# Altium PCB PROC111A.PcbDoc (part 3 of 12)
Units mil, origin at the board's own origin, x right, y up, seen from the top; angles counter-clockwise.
Board outline 7700 x 2300 mil, 6 copper layers (Top Layer, GND 1, SIG 1, SIG 2, GND 2, Bottom Layer), stack 61.062 mil thick; 841 components, 632 nets, 2914 pads, 1627 vias.
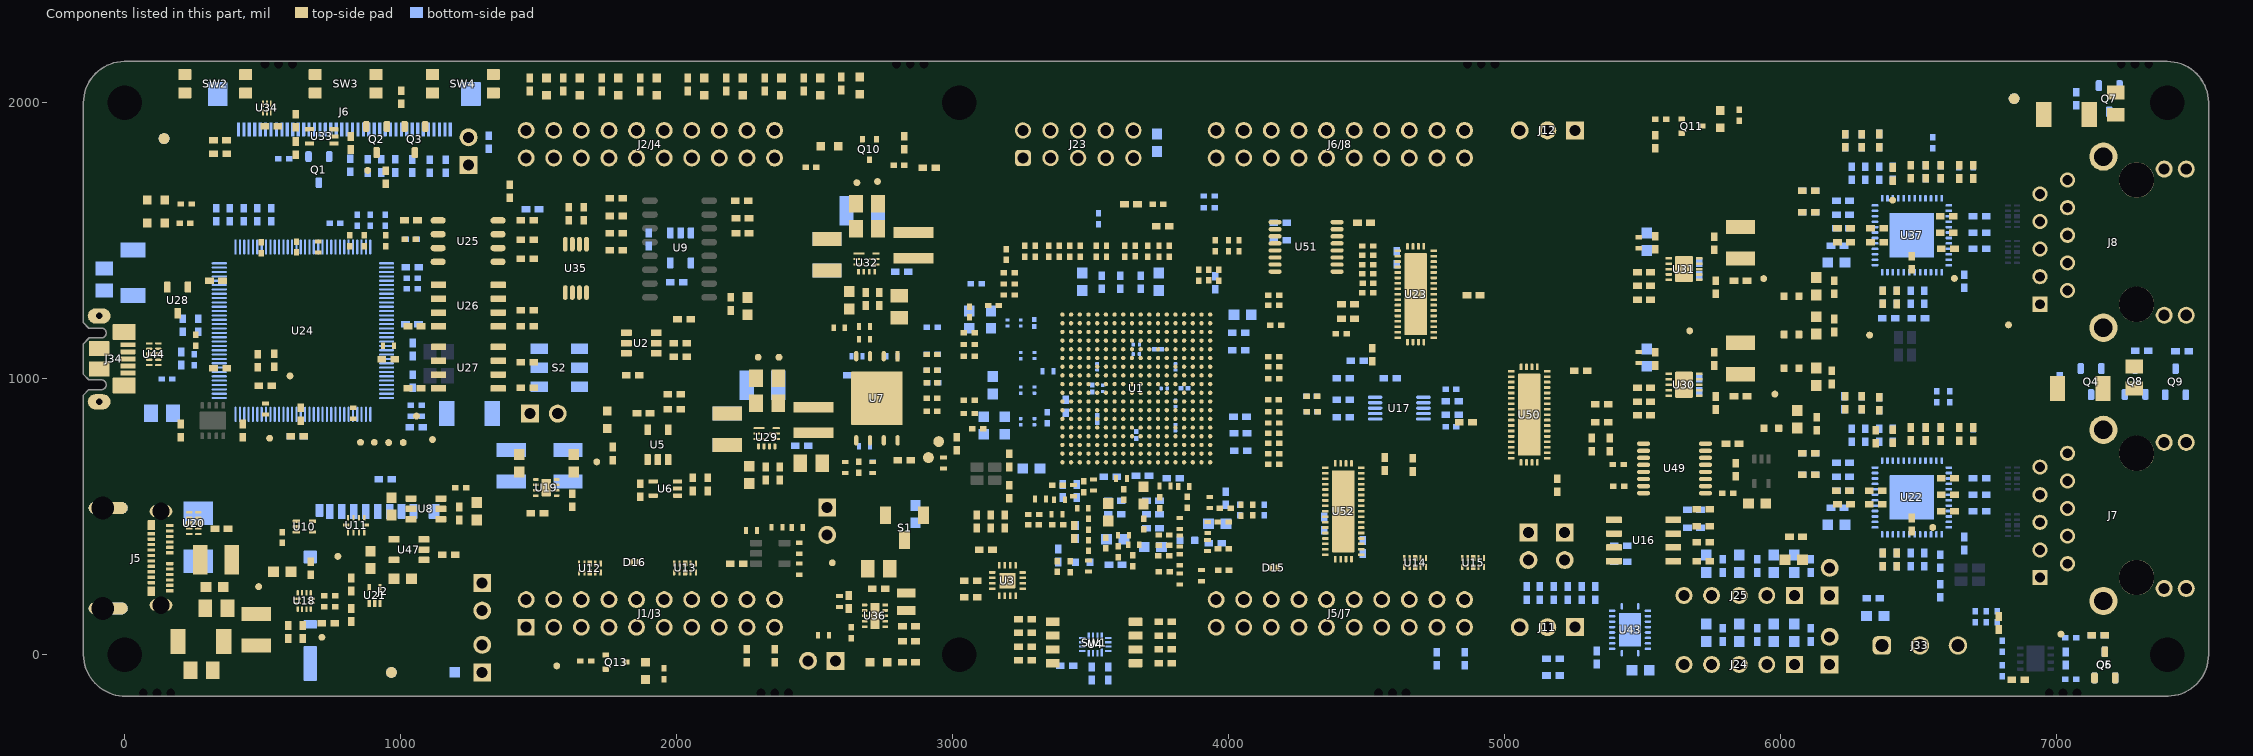
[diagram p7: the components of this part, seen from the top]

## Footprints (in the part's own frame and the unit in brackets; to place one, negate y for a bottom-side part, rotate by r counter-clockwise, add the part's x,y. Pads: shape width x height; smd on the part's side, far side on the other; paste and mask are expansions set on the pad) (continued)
PDT0128A [mm] "Thin QFP, 128-Leads, Body 14x14mm, Pitch 0.4mm"
  oval 1.4x0.2 smd: 1(-7.7,6.2) 2(-7.7,5.8) 3(-7.7,5.4) 4(-7.7,5) 5(-7.7,4.6) 6(-7.7,4.2) 7(-7.7,3.8) 8(-7.7,3.4) 9(-7.7,3) 10(-7.7,2.6) 11(-7.7,2.2) 12(-7.7,1.8) 13(-7.7,1.4) 14(-7.7,1) 15(-7.7,0.6) 16(-7.7,0.2) 17(-7.7,-0.2) 18(-7.7,-0.6) 19(-7.7,-1) 20(-7.7,-1.4) 21(-7.7,-1.8) 22(-7.7,-2.2) 23(-7.7,-2.6) 24(-7.7,-3) 25(-7.7,-3.4) 26(-7.7,-3.8) 27(-7.7,-4.2) 28(-7.7,-4.6) 29(-7.7,-5) 30(-7.7,-5.4) 31(-7.7,-5.8) 32(-7.7,-6.2) 65(7.7,-6.2) 66(7.7,-5.8) 67(7.7,-5.4) 68(7.7,-5) 69(7.7,-4.6) 70(7.7,-4.2) 71(7.7,-3.8) 72(7.7,-3.4) 73(7.7,-3) 74(7.7,-2.6) 75(7.7,-2.2) 76(7.7,-1.8) 77(7.7,-1.4) 78(7.7,-1) 79(7.7,-0.6) 80(7.7,-0.2) 81(7.7,0.2) 82(7.7,0.6) 83(7.7,1) 84(7.7,1.4) 85(7.7,1.8) 86(7.7,2.2) 87(7.7,2.6) 88(7.7,3) 89(7.7,3.4) 90(7.7,3.8) 91(7.7,4.2) 92(7.7,4.6) 93(7.7,5) 94(7.7,5.4) 95(7.7,5.8) 96(7.7,6.2)
  oval 0.2x1.4 smd: 33(-6.2,-7.7) 34(-5.8,-7.7) 35(-5.4,-7.7) 36(-5,-7.7) 37(-4.6,-7.7) 38(-4.2,-7.7) 39(-3.8,-7.7) 40(-3.4,-7.7) 41(-3,-7.7) 42(-2.6,-7.7) 43(-2.2,-7.7) 44(-1.8,-7.7) 45(-1.4,-7.7) 46(-1,-7.7) 47(-0.6,-7.7) 48(-0.2,-7.7) 49(0.2,-7.7) 50(0.6,-7.7) 51(1,-7.7) 52(1.4,-7.7) 53(1.8,-7.7) 54(2.2,-7.7) 55(2.6,-7.7) 56(3,-7.7) 57(3.4,-7.7) 58(3.8,-7.7) 59(4.2,-7.7) 60(4.6,-7.7) 61(5,-7.7) 62(5.4,-7.7) 63(5.8,-7.7) 64(6.2,-7.7) 97(6.2,7.7) 98(5.8,7.7) 99(5.4,7.7) 100(5,7.7) 101(4.6,7.7) 102(4.2,7.7) 103(3.8,7.7) 104(3.4,7.7) 105(3,7.7) 106(2.6,7.7) 107(2.2,7.7) 108(1.8,7.7) 109(1.4,7.7) 110(1,7.7) 111(0.6,7.7) 112(0.2,7.7) 113(-0.2,7.7) 114(-0.6,7.7) 115(-1,7.7) 116(-1.4,7.7) 117(-1.8,7.7) 118(-2.2,7.7) 119(-2.6,7.7) 120(-3,7.7) 121(-3.4,7.7) 122(-3.8,7.7) 123(-4.2,7.7) 124(-4.6,7.7) 125(-5,7.7) 126(-5.4,7.7) 127(-5.8,7.7) 128(-6.2,7.7)
  silkscreen extent -7.7,-6.3 6.3,6.99, body extent -8,-8 8,8, height 1.07
PW0016A_L [mm] "TSOP, 16-Leads, Body 5x4.4mm, Pitch 0.65mm, IPC High Density"
  oval 1.2x0.4 smd: 1(-2.85,2.275) 2(-2.85,1.625) 3(-2.85,0.975) 4(-2.85,0.325) 5(-2.85,-0.325) 6(-2.85,-0.975) 7(-2.85,-1.625) 8(-2.85,-2.275) 9(2.85,-2.275) 10(2.85,-1.625) 11(2.85,-0.975) 12(2.85,-0.325) 13(2.85,0.325) 14(2.85,0.975) 15(2.85,1.625) 16(2.85,2.275)
  silkscreen extent -2,-2.55 1.85,2.55, body extent -3.21,-2.5 3.21,2.5, height 1
RGT0016A [mm] "QFN, 16-Leads, Body 3x3mm, Pitch 0.5mm, Thermal Pad 1.45x1.45mm, TI Recommended"
  rrect42% 0.6x0.24 smd: 1(-1.4,0.75) 2(-1.4,0.25) 3(-1.4,-0.25) 4(-1.4,-0.75) 9(1.4,-0.75) 10(1.4,-0.25) 11(1.4,0.25) 12(1.4,0.75)
  rrect42% 0.24x0.6 smd: 5(-0.75,-1.4) 6(-0.25,-1.4) 7(0.25,-1.4) 8(0.75,-1.4) 13(0.75,1.4) 14(0.25,1.4) 15(-0.25,1.4) 16(-0.75,1.4)
  rrect7% 1.34x1.34 on Top Paste: 17(0,0)
  rrect7% 1.45x1.45 smd paste-0.725: 17(0,0)
  silkscreen extent -1.72,-1.73 1.72,1.73, body extent -1.5,-1.5 1.5,1.5, height 1
RGY0020A [mm] "QFN, 20-Leads, Body 4.5x3.5mm, Pitch 0.5mm, Thermal Pad 3.05x2.05mm, TI Recommended"
  oval 0.24x0.6 smd: 1(-0.75,2.15) 10(-0.75,-2.15) 11(0.75,-2.15) 20(0.75,2.15)
  oval 0.6x0.24 smd: 2(-1.65,1.75) 3(-1.65,1.25) 4(-1.65,0.75) 5(-1.65,0.25) 6(-1.65,-0.25) 7(-1.65,-0.75) 8(-1.65,-1.25) 9(-1.65,-1.75) 12(1.65,-1.75) 13(1.65,-1.25) 14(1.65,-0.75) 15(1.65,-0.25) 16(1.65,0.25) 17(1.65,0.75) 18(1.65,1.25) 19(1.65,1.75)
  rect 2.05x3.05 smd paste-1.025: 21(0,0)
  silkscreen extent -1.97,-2.47 1.97,2.48, body extent -1.75,-2.25 1.75,2.25, height 1
RGZ0048B-MFG [mm]
  rrect42% 0.6x0.24 smd paste+0 mask+0: 1(-3.4,2.75) 2(-3.4,2.25) 3(-3.4,1.75) 4(-3.4,1.25) 5(-3.4,0.75) 6(-3.4,0.25) 7(-3.4,-0.25) 8(-3.4,-0.75) 9(-3.4,-1.25) 10(-3.4,-1.75) 11(-3.4,-2.25) 12(-3.4,-2.75) 25(3.4,-2.75) 26(3.4,-2.25) 27(3.4,-1.75) 28(3.4,-1.25) 29(3.4,-0.75) 30(3.4,-0.25) 31(3.4,0.25) 32(3.4,0.75) 33(3.4,1.25) 34(3.4,1.75) 35(3.4,2.25) 36(3.4,2.75)
  rrect42% 0.24x0.6 smd paste+0 mask+0: 13(-2.75,-3.4) 14(-2.25,-3.4) 15(-1.75,-3.4) 16(-1.25,-3.4) 17(-0.75,-3.4) 18(-0.25,-3.4) 19(0.25,-3.4) 20(0.75,-3.4) 21(1.25,-3.4) 22(1.75,-3.4) 23(2.25,-3.4) 24(2.75,-3.4) 37(2.75,3.4) 38(2.25,3.4) 39(1.75,3.4) 40(1.25,3.4) 41(0.75,3.4) 42(0.25,3.4) 43(-0.25,3.4) 44(-0.75,3.4) 45(-1.25,3.4) 46(-1.75,3.4) 47(-2.25,3.4) 48(-2.75,3.4)
  rrect2% 4.1x4.1 smd paste-1000 mask+0: 49(0,0)
  silkscreen extent -4.38,-3.57 3.57,3.57, body extent -3.5,-3.5 3.5,3.5, height 1.02
RPU0010A-MFG [mm]
  rrect50% 0.65x0.2 smd paste+0 mask+0: 1(-0.875,0.25) 3(-0.875,-0.75) 5(0.875,-0.25)
  rrect50% 1x0.2 smd paste+0 mask+0: 2(-0.7,-0.25) 4(0.7,-0.75) 6(0.7,0.25)
  rrect40% 0.25x0.55 smd paste+0 mask+0: 7(0.75,0.925) 8(0.25,0.925) 9(-0.25,0.925) 10(-0.75,0.925)
  silkscreen extent -1.97,-1.5 1,1.6, body extent -1.3,-1.15 1.3,1.3, height 0.25
RSE0010A [mm] "QFN, 10-Leads, Body 1.5x2mm, Pitch 0.5mm, TI Recommended"
  rect 0.55x0.2 smd: 1(-0.675,0.75) 2(-0.675,0.25) 3(-0.675,-0.25) 4(-0.675,-0.75) 6(0.675,-0.75) 7(0.675,-0.25) 8(0.675,0.25) 9(0.675,0.75)
  rect 0.3x0.6 smd: 5(0,-0.9) 10(0,0.9)
  silkscreen extent -1.07,-1.17 0.77,1.18, body extent -0.77,-1.02 0.78,1.03, height 0.61
RSV0016A [mm] "QFN, 16-Leads, Body 1.8x2.6mm, Pitch 0.4mm, TI Recommended"
  rect 0.7x0.2 smd: 1(-0.75,0.6)
  rect 0.6x0.2 smd: 2(-0.8,0.2) 3(-0.8,-0.2) 4(-0.8,-0.6) 9(0.8,-0.6) 10(0.8,-0.2) 11(0.8,0.2) 12(0.8,0.6)
  rect 0.2x0.6 smd: 5(-0.6,-1.2) 6(-0.2,-1.2) 7(0.2,-1.2) 8(0.6,-1.2) 13(0.6,1.2) 14(0.2,1.2) 15(-0.2,1.2) 16(-0.6,1.2)
  silkscreen extent -1.08,-1.33 1.08,1.45, body extent -0.92,-1.32 0.92,1.33, height 0.56
RUA0042A-MFG [mm]
  rrect40% 0.6x0.25 smd paste+0 mask+0: 1(-1.65,4) 2(-1.65,3.5) 3(-1.65,3) 4(-1.65,2.5) 5(-1.65,2) 6(-1.65,1.5) 7(-1.65,1) 8(-1.65,0.5) 9(-1.65,0) 10(-1.65,-0.5) 11(-1.65,-1) 12(-1.65,-1.5) 13(-1.65,-2) 14(-1.65,-2.5) 15(-1.65,-3) 16(-1.65,-3.5) 17(-1.65,-4) 22(1.65,-4) 23(1.65,-3.5) 24(1.65,-3) 25(1.65,-2.5) 26(1.65,-2) 27(1.65,-1.5) 28(1.65,-1) 29(1.65,-0.5) 30(1.65,0) 31(1.65,0.5) 32(1.65,1) 33(1.65,1.5) 34(1.65,2) 35(1.65,2.5) 36(1.65,3) 37(1.65,3.5) 38(1.65,4)
  rrect40% 0.25x0.6 smd paste+0 mask+0: 18(-0.75,-4.4) 19(-0.25,-4.4) 20(0.25,-4.4) 21(0.75,-4.4) 39(0.75,4.4) 40(0.25,4.4) 41(-0.25,4.4) 42(-0.75,4.4)
  rrect5% 2.05x7.55 smd paste-1000 mask+0: 43(0,0)
  silkscreen extent -2.65,-4.55 1.8,4.55, body extent -2.05,-4.8 2.05,4.8, height 0.25
RWB0012A [mm] "QFN, 12-Leads, Body 1.6x1.6mm, Pitch 0.4mm"
  rrect57% 0.7x0.2 smd paste-0.1: 1(-0.65,0.2) 2(-0.65,-0.2) 7(0.65,-0.2) 8(0.65,0.2)
  rrect57% 0.2x0.5 smd: 3(-0.6,-0.75) 4(-0.2,-0.75) 5(0.2,-0.75) 6(0.6,-0.75) 9(0.6,0.75) 10(0.2,0.75) 11(-0.2,0.75) 12(-0.6,0.75)
  silkscreen extent -0.92,-0.91 0.92,0.91, body extent -0.8,-0.8 0.8,0.8, height 0.4
SMB-Bi [mil] "Molded Diode, 2-Leads, Body 5.4x3.6mm, IPC Medium Density, based on OnSemi component dimensions"
  rect 85x107.99 smd: 1(-87.01,0) 2(87.01,0)
  silkscreen extent -125,-79 125,79, body extent -104,-73 104,73, height 89
SOIC-8 [mm] "duplicate of SO-8.  SOIC, 8-Leads, Body 5.0x4.0mm (max), Pitch 1.27mm, IPC Medium Density"
  rrect17% 1.45x0.6 smd: 1(-2.725,1.905) 2(-2.725,0.635) 3(-2.725,-0.635) 4(-2.725,-1.905) 5(2.725,-1.905) 6(2.725,-0.635) 7(2.725,0.635) 8(2.725,1.905)
  silkscreen extent -3.5,-2.5 0.9,2.5, body extent -3,-2.45 3,2.45, height 1.63
SOT-23 [mm] "SOT23, 3-Leads, Body 2.9x1.3mm, Pitch 0.95mm, Lead Span 2.5mm, IPC Medium Density"
  rrect50% 1x0.6 smd: 1(-1.2,0.95) 2(-1.2,-0.95) 3(1.2,0)
  silkscreen extent -1.63,-1.5 0.7,1.5, body extent -1.16,-1.45 1.21,1.45, height 1
SOT-323 [mm] "Diodes Inc recommended land pattern.  2016-02-24"
  rrect21% 0.6x0.47 smd: 1(-0.95,0.65) 2(-0.95,-0.65) 3(0.95,0)
  silkscreen extent -1.14,-1.22 0.77,1.22, body extent -1.13,-1.13 1.12,1.12, height 1.13
Sullins_PBC02SAAN [mm] "Sullins 100mil, 1x2, 230 mil above insulator"
  rect 1.65x1.65 hole 1.016: 1(0,1.27)
  round 1.65 hole 1.016: 2(0,-1.27)
  silkscreen extent -1.37,-2.54 1.27,3.1, body extent -1.27,-2.54 1.27,2.54, height 8.38
Sullins_PxC05SAAN [mm] "Header, 2.54mm, 5x1, TH"
  rect 1.55x1.55 hole 1.016: 1(-5.08,0)
  round 1.55 hole 1.016: 2(-2.54,0) 3(0,0) 4(2.54,0) 5(5.08,0)
  silkscreen extent -6.35,-1.75 6.35,1.27, body extent -6.35,-1.27 6.35,1.27, height 5.84
Sullins_xxPC005DAAN-RC [mm] "Header, 2.54mm, 5x2, TH"
  rrect50% 1.5x1.5 hole 1: 1(-1.27,5.08)
  round 1.5 hole 1: 2(1.27,5.08) 3(-1.27,2.54) 4(1.27,2.54) 5(-1.27,0) 6(1.27,0) 7(-1.27,-2.54) 8(1.27,-2.54) 9(-1.27,-5.08) 10(1.27,-5.08)
  body extent -2.5,-6.35 2.5,6.35, height 8.34
SW_CAS-120TA [mm] "COPAL ELECTRONICS"
  rect 1.6x1 smd: 1(-1.15,1.75) 2(1.15,0) 3(-1.15,-1.75)
  silkscreen extent -2,-2.85 1.4,2.93, body extent -1.4,-2.85 1.4,2.85, height 2.51
SW_CAS-D20TA [mm] "SMD, 6-Leads, Body 5.4x3.9mm, Pitch 1.75mm"
  rect 1.6x1 smd: 1(-1.85,1.75) 2(-1.85,0) 3(-1.85,-1.75) 4(1.85,1.75) 5(1.85,0) 6(1.85,-1.75)
  silkscreen extent -1.95,-2.7 1.95,2.9, body extent -2.1,-2.7 2.1,2.7, height 2.5
TI_Stacked_Overlay_Small [mil]
  silkscreen extent -418,-98 418,98
TP_25MIL-SMT [mil]
  round 25 smd mask-2.5: 1(0,0)
TP_SM_1MM [mm] "1mm Test Point, SMT"
  round 1 smd paste-0.5: 1(0,0)
WE-MAPI_4020 [mm] "SMD, 2-Leads, Body 4.1x4.1mm"
  rect 0.98x3.7 smd: 1(-1.185,0) 2(1.185,0)
  silkscreen extent -2.15,-2.15 2.15,2.15, body extent -2.15,-2.15 2.15,2.15, height 2.1
WEEE_Minimum [mil] "WEEElie bin"
  silkscreen extent -95,-172 99,104
WL-SMCW_GREEN [mm] "WURTH"
  rect 0.8x0.8 smd: 1(-0.8,0) 2(0.8,0)
  silkscreen extent -1.9,-0.8 1.2,0.8, body extent -0.85,-0.45 0.85,0.45, height 0.8
WL-SMCW_RED [mm] "WURTH"
  rect 0.8x0.8 smd: 1(-0.8,0) 2(0.8,0)
  silkscreen extent -1.9,-0.8 1.2,0.8, body extent -0.85,-0.45 0.85,0.45, height 0.8
Wurth_60900213421 [mil] "Shunt, 2.54mm, Black"
  round 1 on Mech3: 0(0,0)
  body extent -98,-48 98,48, height 338
"ZCZ (S-PBGA-N324)" [mm] "0.8mm pitch, 15x15mm, Plastic Ball Grid Array"
  round 0.4 smd: A1(0,0) A2(0.8,0) A3(1.6,0) A4(2.4,0) A5(3.2,0) A6(4,0) A7(4.8,0) A8(5.6,0) A9(6.4,0) A10(7.2,0) A11(8,0) A12(8.8,0) A13(9.6,0) A14(10.4,0) A15(11.2,0) A16(12,0) A17(12.8,0) A18(13.6,0) B1(0,-0.8) B2(0.8,-0.8) B3(1.6,-0.8) B4(2.4,-0.8) B5(3.2,-0.8) B6(4,-0.8) B7(4.8,-0.8) B8(5.6,-0.8) B9(6.4,-0.8) B10(7.2,-0.8) B11(8,-0.8) B12(8.8,-0.8) B13(9.6,-0.8) B14(10.4,-0.8) B15(11.2,-0.8) B16(12,-0.8) B17(12.8,-0.8) B18(13.6,-0.8) C1(0,-1.6) C2(0.8,-1.6) C3(1.6,-1.6) C4(2.4,-1.6) C5(3.2,-1.6) C6(4,-1.6) C7(4.8,-1.6) C8(5.6,-1.6) C9(6.4,-1.6) C10(7.2,-1.6) C11(8,-1.6) C12(8.8,-1.6) C13(9.6,-1.6) C14(10.4,-1.6) C15(11.2,-1.6) C16(12,-1.6) C17(12.8,-1.6) C18(13.6,-1.6) D1(0,-2.4) D2(0.8,-2.4) D3(1.6,-2.4) D4(2.4,-2.4) D5(3.2,-2.4) D6(4,-2.4) D7(4.8,-2.4) D8(5.6,-2.4) D9(6.4,-2.4) D10(7.2,-2.4) D11(8,-2.4) D12(8.8,-2.4) D13(9.6,-2.4) D14(10.4,-2.4) D15(11.2,-2.4) D16(12,-2.4) D17(12.8,-2.4) D18(13.6,-2.4) E1(0,-3.2) E2(0.8,-3.2) E3(1.6,-3.2) E4(2.4,-3.2) E5(3.2,-3.2) E6(4,-3.2) E7(4.8,-3.2) E8(5.6,-3.2) E9(6.4,-3.2) E10(7.2,-3.2) E11(8,-3.2) E12(8.8,-3.2) E13(9.6,-3.2) E14(10.4,-3.2) E15(11.2,-3.2) E16(12,-3.2) E17(12.8,-3.2) E18(13.6,-3.2) F1(0,-4) F2(0.8,-4) F3(1.6,-4) F4(2.4,-4) F5(3.2,-4) F6(4,-4) F7(4.8,-4) F8(5.6,-4) F9(6.4,-4) F10(7.2,-4) F11(8,-4) F12(8.8,-4) F13(9.6,-4) F14(10.4,-4) F15(11.2,-4) F16(12,-4) F17(12.8,-4) F18(13.6,-4) G1(0,-4.8) G2(0.8,-4.8) G3(1.6,-4.8) G4(2.4,-4.8) G5(3.2,-4.8) G6(4,-4.8) G7(4.8,-4.8) G8(5.6,-4.8) G9(6.4,-4.8) G10(7.2,-4.8) G11(8,-4.8) G12(8.8,-4.8) G13(9.6,-4.8) G14(10.4,-4.8) G15(11.2,-4.8) G16(12,-4.8) G17(12.8,-4.8) G18(13.6,-4.8) H1(0,-5.6) H2(0.8,-5.6) H3(1.6,-5.6) H4(2.4,-5.6) H5(3.2,-5.6) H6(4,-5.6) H7(4.8,-5.6) H8(5.6,-5.6) H9(6.4,-5.6) H10(7.2,-5.6) H11(8,-5.6) H12(8.8,-5.6) H13(9.6,-5.6) H14(10.4,-5.6) H15(11.2,-5.6) H16(12,-5.6) H17(12.8,-5.6) H18(13.6,-5.6) J1(0,-6.4) J2(0.8,-6.4) J3(1.6,-6.4) J4(2.4,-6.4) J5(3.2,-6.4) J6(4,-6.4) J7(4.8,-6.4) J8(5.6,-6.4) J9(6.4,-6.4) J10(7.2,-6.4) J11(8,-6.4) J12(8.8,-6.4) J13(9.6,-6.4) J14(10.4,-6.4) J15(11.2,-6.4) J16(12,-6.4) J17(12.8,-6.4) J18(13.6,-6.4) K1(0,-7.2) K2(0.8,-7.2) K3(1.6,-7.2) K4(2.4,-7.2) K5(3.2,-7.2) K6(4,-7.2) K7(4.8,-7.2) K8(5.6,-7.2) K9(6.4,-7.2) K10(7.2,-7.2) K11(8,-7.2) K12(8.8,-7.2) K13(9.6,-7.2) K14(10.4,-7.2) K15(11.2,-7.2) K16(12,-7.2) K17(12.8,-7.2) K18(13.6,-7.2) L1(0,-8) L2(0.8,-8) L3(1.6,-8) L4(2.4,-8) L5(3.2,-8) L6(4,-8) L7(4.8,-8) L8(5.6,-8) L9(6.4,-8) L10(7.2,-8) L11(8,-8) L12(8.8,-8) L13(9.6,-8) L14(10.4,-8) L15(11.2,-8) L16(12,-8) L17(12.8,-8) L18(13.6,-8) M1(0,-8.8) M2(0.8,-8.8) M3(1.6,-8.8) M4(2.4,-8.8) M5(3.2,-8.8) M6(4,-8.8) M7(4.8,-8.8) M8(5.6,-8.8) M9(6.4,-8.8) M10(7.2,-8.8) M11(8,-8.8) M12(8.8,-8.8) M13(9.6,-8.8) M14(10.4,-8.8) M15(11.2,-8.8) M16(12,-8.8) M17(12.8,-8.8) M18(13.6,-8.8) N1(0,-9.6) N2(0.8,-9.6) N3(1.6,-9.6) N4(2.4,-9.6) N5(3.2,-9.6) N6(4,-9.6) N7(4.8,-9.6) N8(5.6,-9.6) N9(6.4,-9.6) N10(7.2,-9.6) N11(8,-9.6) N12(8.8,-9.6) N13(9.6,-9.6) N14(10.4,-9.6) N15(11.2,-9.6) N16(12,-9.6) N17(12.8,-9.6) N18(13.6,-9.6) P1(0,-10.4) P2(0.8,-10.4) P3(1.6,-10.4) P4(2.4,-10.4) P5(3.2,-10.4) P6(4,-10.4) P7(4.8,-10.4) P8(5.6,-10.4) P9(6.4,-10.4) P10(7.2,-10.4) P11(8,-10.4) P12(8.8,-10.4) P13(9.6,-10.4) P14(10.4,-10.4) P15(11.2,-10.4) P16(12,-10.4) P17(12.8,-10.4) P18(13.6,-10.4) R1(0,-11.2) R2(0.8,-11.2) R3(1.6,-11.2) R4(2.4,-11.2) R5(3.2,-11.2) R6(4,-11.2) R7(4.8,-11.2) R8(5.6,-11.2) R9(6.4,-11.2) R10(7.2,-11.2) R11(8,-11.2) R12(8.8,-11.2) R13(9.6,-11.2) R14(10.4,-11.2) R15(11.2,-11.2) R16(12,-11.2) R17(12.8,-11.2) R18(13.6,-11.2) T1(0,-12) T2(0.8,-12) T3(1.6,-12) T4(2.4,-12) T5(3.2,-12) T6(4,-12) T7(4.8,-12) T8(5.6,-12) T9(6.4,-12) T10(7.2,-12) T11(8,-12) T12(8.8,-12) T13(9.6,-12) T14(10.4,-12) T15(11.2,-12) T16(12,-12) T17(12.8,-12) T18(13.6,-12) U1(0,-12.8) U2(0.8,-12.8) U3(1.6,-12.8) U4(2.4,-12.8) U5(3.2,-12.8) U6(4,-12.8) U7(4.8,-12.8) U8(5.6,-12.8) U9(6.4,-12.8) U10(7.2,-12.8) U11(8,-12.8) U12(8.8,-12.8) U13(9.6,-12.8) U14(10.4,-12.8) U15(11.2,-12.8) U16(12,-12.8) U17(12.8,-12.8) U18(13.6,-12.8) V1(0,-13.6) V2(0.8,-13.6) V3(1.6,-13.6) V4(2.4,-13.6) V5(3.2,-13.6) V6(4,-13.6) V7(4.8,-13.6) V8(5.6,-13.6) V9(6.4,-13.6) V10(7.2,-13.6) V11(8,-13.6) V12(8.8,-13.6) V13(9.6,-13.6) V14(10.4,-13.6) V15(11.2,-13.6) V16(12,-13.6) V17(12.8,-13.6) V18(13.6,-13.6)
  silkscreen extent -0.8,-14.4 14.4,0.8, body extent -0.7,-14.3 14.3,0.7, height 1

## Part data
C1 C2 C3 C4 C5 C6 C14 C23 C25 C52 C53 C68 C236: library part CMP-0007057-4, "CAP, CERM, 3.3 uF, 10 V, +/- 10%, X7S, 0603", Cap_Case=0603, Manufacturer=TDK, Supplier Part Number 1=445-14256-1-ND, TempCo=X7S, Tolerance_%=10%, Value1="0.004796 ohm", Value2=10V, ValueDisplayed=3.3uF
C7 C8 C9 C10 C11 C12 C13 C15 C16 C17 C18 C24 C26 C27 C28 C34 C35 C36 C37 C38 C48 C69 C78 C79 C80 C90 C91 C98 C117 C119 C121 C125 C127 C131 C133 C165 C176 C194 C196 C198 C202 C204 C208 C210 C237 C250: library part CMP-0006623-2, "CAP, CERM, 0.1 uF, 6.3 V, +/- 10%, X7R, 0402", Cap_Case=0402, Manufacturer=MuRata, Supplier Part Number 1=GRM155R70J104KA01D-ND, TempCo=X7R, Tolerance_%=10%, Value1=Unknown, Value2=6.3V, ValueDisplayed=0.1uF
C19 C20 C21 C22 C29 C30 C31 C32 C39 C40 C41 C42 C44 C45 C46 C47: library part CMP-0093721-1, "Chip Multilayer Ceramic Capacitors for General Purpose, 0201, 1.0uF, X6S, 22%, 20%, 6.3V", Manufacturer=Murata, Operating Temperature Range="-55°C to +105°C", TempCo=22%, Temperature Characteristic=X6S, Tolerance_%=20%, ValueDisplayed=1.0uF
C33 C76 C77 C89: library part CMP-0007498-4, "CAP, CERM, 4.7 uF, 10 V, +/- 20%, X7R, 0603", Cap_Case=0603, Manufacturer=MuRata, TempCo=X7R, Tolerance_%=20%, Value1=Unknown, Value2=10V, ValueDisplayed=4.7uF
C43 C57 C60 C61 C62 C64 C65 C66 C70 C71 C99 C100 C111 C134 C136 C137 C138 C139 C140 C141 C142 C145 C147 C150 C151 C154 C155 C163 C174 C181 C182 C183 C184 C186 C188 C223 C225 C226 C233 C238 C239 C240 C241 C242 C243 C244 C245 C246: library part CMP-0006659-2, "CAP, CERM, 0.1 uF, 25 V, +/- 10%, X7R, 0402", Cap_Case=0402, Manufacturer=MuRata, Supplier Part Number 1=490-10698-1-ND, TempCo=X7R, Tolerance_%=10%, Value1=Unknown, Value2=25V, ValueDisplayed=0.1uF
C49 C50 C51 C54 C55 C56: library part CMP-0064970-1, "CAP, CERM, 0.1 uF, 16 V,+/- 10%, X7R, 0201", Cap_Case=0201, Manufacturer=MuRata, Supplier Part Number 1=81-GRM033Z71C104KE4D, TempCo=X7R, Tolerance_%=10%, Value1=Unknown, Value2=16V, ValueDisplayed=0.1uF
C58 C59 C112 C113 C189 C190: library part CMP-0006375-2, "CAP, CERM, 12 pF, 25 V, +/- 5%, C0G/NP0, 0402", Cap_Case=0402, Manufacturer=MuRata, Supplier Part Number 1=81-GRM1555C1E120JA1D, TempCo=C0G/NP0, Tolerance_%=5%, Value1=Unknown, Value2=25V, ValueDisplayed=12pF
C63 C135 C149 C152: library part CMP-0006658-2, "CAP, CERM, 0.01 uF, 25 V, +/- 10%, X7R, 0402", Cap_Case=0402, Manufacturer=MuRata, Supplier Part Number 1=490-1312-1-ND, TempCo=X7R, Tolerance_%=10%, Value1=Unknown, Value2=25V, ValueDisplayed=0.01uF
C67 C161 C172: library part CMP-0064936-4, "CAP, CERM, 4.7 uF, 16 V,+/- 10%, X7R, 0603", Cap_Case=0603, Manufacturer=MuRata, TempCo=X7R, Tolerance_%=10%, Value1=Unknown, Value2=16V, ValueDisplayed=4.7uF
C72 C73 C74 C75 C81 C82 C83 C84 C85 C86 C87 C88 C92 C93 C94 C95 C96 C97 C251 C252: library part CMP-0079619-1, "CAP, CERM, 330 pF, 25 V,+/- 5%, C0G/NP0, 0402", Cap_Case=0402, Manufacturer=MuRata, Supplier Part Number 1=490-8176-1-ND, TempCo=C0G/NP0, Tolerance_%=5%, Value2=25V, ValueDisplayed=330pF
C101 C106 C108 C110 C248 C249: library part CMP-0007135-4, "CAP, CERM, 0.1 uF, 16 V, +/- 10%, X7R, AEC-Q200 Grade 1, 0603", Cap_Case=0603, Manufacturer=MuRata, Supplier Part Number 1=490-8015-1-ND, TempCo=X7R, Tolerance_%=10%, Value1=Unknown, Value2=16V, ValueDisplayed=0.1uF
C102 C104 C105 C107 C164 C167 C168 C175 C179 C180: library part CMP-0081639-1, "CAP, CERM, 10 µF, 35 V,+/- 10%, X7R, 1210", Cap_Case=1210, Manufacturer=MuRata, Supplier Part Number 1=GRM32ER7YA106KA12K-ND, TempCo=X7R, Tolerance_%=10%, Value1="0.001 ohm", Value2=35V, ValueDisplayed=10µF
C103: library part CMP-0007470-5, "CAP, CERM, 0.1 uF, 100 V, +/- 10%, X7R, 0603", Cap_Case=0603, Manufacturer=MuRata, Supplier Part Number 1=490-6439-1-ND, TempCo=X7R, Tolerance_%=10%, Value1=Unknown, Value2=100V, ValueDisplayed=0.1uF
C109: library part CMP-0006638-1, "CAP, CERM, 1000 pF, 16 V, +/- 10%, X7R, 0402", Cap_Case=0402, Manufacturer=MuRata, Supplier Part Number 1=GRM155R71C102KA01D-ND, TempCo=X7R, Tolerance_%=10%, Value1=Unknown, Value2=16V, ValueDisplayed=1000pF
C114 C122 C128 C191 C199 C205: library part CMP-0007497-5, "CAP, CERM, 10 uF, 10 V, +/- 20%, X7R, 0603", Cap_Case=0603, Manufacturer=MuRata, Supplier Part Number 1=81-GRM188Z71A106MA3D, TempCo=X7R, Tolerance_%=20%, Value1=Unknown, Value2=10V, ValueDisplayed=10uF
C115 C123 C129 C192 C200 C206: library part CMP-0006622-2, "CAP, CERM, 0.01 uF, 6.3 V, +/- 10%, X7R, 0402", Cap_Case=0402, Manufacturer=MuRata, Supplier Part Number 1=GRM155R70J103KA01D-ND, TempCo=X7R, Tolerance_%=10%, Value1=Unknown, Value2=6.3V, ValueDisplayed=0.01uF
C116 C118 C120 C124 C126 C130 C132 C193 C195 C197 C201 C203 C207 C209: library part CMP-0006624-2, "CAP, CERM, 1 uF, 6.3 V, +/- 20%, X7R, 0402", Cap_Case=0402, Manufacturer=MuRata, Supplier Part Number 1=490-9665-1-ND, TempCo=X7R, Tolerance_%=20%, Value1=Unknown, Value2=6.3V, ValueDisplayed=1uF
C143 C144: library part CMP-0087060-3, "Cap Ceramic 8pF 50V C0G 0.5pF SMD 0402 125C Paper T/R", Manufacturer="Murata Electronics North America", TempCo=30ppm/°C
C146 C148 C156 C162 C173 C187 C232 C253 C254: library part CMP-0006349-2, "CAP, CERM, 1 uF, 10 V, +/- 10%, X7S, AEC-Q200 Grade 1, 0402", Cap_Case=0402, Manufacturer=MuRata, Supplier Part Number 1=81-GCM155C71A105KE8D, TempCo=X7S, Tolerance_%=10%, Value1=Unknown, Value2=10V, ValueDisplayed=1uF
C153 C231: library part CMP-0006526-2, "CAP, CERM, 2.2 uF, 16 V, +/- 10%, X6S, 0402", Cap_Case=0402, Manufacturer=MuRata, Supplier Part Number 1=GRM155C81C225KE11D-ND, TempCo=X6S, Tolerance_%=10%, Value1=Unknown, Value2=16V, ValueDisplayed=2.2uF
C157 C158 C169 C170 C185: library part CMP-0008377-2, "CAP, CERM, 22 uF, 10 V, +/- 20%, X7R, 0805", Cap_Case=0805, Manufacturer=MuRata, Supplier Part Number 1=81-GRM21BZ71A226ME5L, TempCo=X7R, Tolerance_%=20%, Value1=Unknown, Value2=10V, ValueDisplayed=22uF
C159 C171: library part CMP-0009221-2, "CAP, CERM, 47 uF, 10 V, +/- 20%, X7R, 1210", Cap_Case=1210, Manufacturer=MuRata, Supplier Part Number 1=490-6543-1-ND, TempCo=X7R, Tolerance_%=20%, Value1=Unknown, Value2=10V, ValueDisplayed=47uF
C160 C177: library part CMP-0007424-4, "CAP, CERM, 0.47 uF, 25 V, +/- 10%, X7R, 0603", Cap_Case=0603, Manufacturer=MuRata, Supplier Part Number 1=490-3291-1-ND, TempCo=X7R, Tolerance_%=10%, Value1=Unknown, Value2=25V, ValueDisplayed=0.47uF
C166 C178: library part CMP-0006706-2, "CAP, CERM, 2700 pF, 100 V, +/- 10%, X7R, 0402", Cap_Case=0402, Manufacturer=MuRata, Supplier Part Number 1=GRM155R72A272KA01D-ND, TempCo=X7R, Tolerance_%=10%, Value1=Unknown, Value2=100V, ValueDisplayed=2700pF
C211 C212 C213 C224: library part CMP-0007144-4, "CAP, CERM, 0.1 uF, 50 V, +/- 10%, X7R, 0603", Cap_Case=0603, Manufacturer=MuRata, Supplier Part Number 1=490-4779-1-ND, TempCo=X7R, Tolerance_%=10%, Value1="0.02 ohm", Value2=50V, ValueDisplayed=0.1uF
C214 C216 C217 C219 C220 C221: library part CMP-0086079-1, "CAP, CERM, 1000 pF, 50 V,+/- 5%, C0G/NP0, AEC-Q200 Grade 1, 0603", Cap_Case=0603, Manufacturer=MuRata, TempCo=C0G/NP0, Tolerance_%=5%, Value2=50V, ValueDisplayed=1000pF
C215 C218: library part CMP-0007171-4, "CAP, CERM, 100 pF, 50 V, +/- 5%, C0G/NP0, 0603", Cap_Case=0603, Manufacturer=MuRata, Supplier Part Number 1=490-1427-1-ND, TempCo=C0G/NP0, Tolerance_%=5%, Value1=Unknown, Value2=50V, ValueDisplayed=100pF
C222: library part CMP-0006361-2, "CAP, CERM, 4700 pF, 50 V, +/- 10%, X7R, AEC-Q200 Grade 1, 0402", Cap_Case=0402, Manufacturer=MuRata, Supplier Part Number 1=490-4915-1-ND, TempCo=X7R, Tolerance_%=10%, Value1=Unknown, Value2=50V, ValueDisplayed=4700pF
C227: library part CMP-0008378-2, "CAP, CERM, 10 uF, 25 V, +/- 10%, X7R, 0805", Cap_Case=0805, Manufacturer=MuRata, Supplier Part Number 1=81-GRM21BZ71E106KE5L, TempCo=X7R, Tolerance_%=10%, Value1=Unknown, Value2=25V, ValueDisplayed=10uF
C228: library part CMP-0006420-2, "CAP, CERM, 15 pF, 50 V, +/- 5%, C0G/NP0, 0402", Cap_Case=0402, Manufacturer=MuRata, Supplier Part Number 1=81-GRM1555C1H150JA1D, TempCo=C0G/NP0, Tolerance_%=5%, Value1=Unknown, Value2=50V, ValueDisplayed=15pF
C229 C230 C234 C235 C247: library part CMP-0009436-2, "CAP, CERM, 1000 pF, 2000 V, +/- 10%, X7R, 1808", Cap_Case=1808, Manufacturer=MuRata, Supplier Part Number 1=490-8145-1-ND, TempCo=X7R, Tolerance_%=10%, Value1=Unknown, Value2=2000V, ValueDisplayed=1000pF
D1: library part CMP-0005599-2, "Diode, TVS, Bi, 6.5 V, SMB", Manufacturer=Littelfuse, Value1=600W
D2 D3 D4 D5 D6 D7 D8 D9 D10 D11 D12 D13 D14: library part CMP-0002894-2, "LED, Green, SMD", Color=green, Manufacturer="Wurth Elektronik", Value1=W, Value2=2V
D15 D16: library part CMP-0073602-3, "1-Channel ESD Protection Diode for USB Type-C and Thunderbolt 3, DPY0002A (X1SON-2)", Alternate Manufacturer="Texas Instruments", Alternate PartNumber=TPD1E01B04DPYT, Operating Temperature Range="-40 to 125 C", Rating=Catalog
DS1 DS2 DS3: library part CMP-0002947-3, "LED, Red, SMD", Color=Red, Manufacturer="Wurth Elektronik", Power_TotalModule=72mW, Value1=0.072W, Value2=2V
FB1 FB2 FB3 FB4 FB5 FB6: library part CMP-0089199-1, "120 Ohms @ 100MHz 1  Ferrite Bead 0603 (1608 Metric) 2A 40mOhm", Digikey Part Number=490-3991-1-ND, Impedance At Frequency="120Ω @ 100MHz", Manufacturer=Murata, Mouser Part Number=81-BLM18EG121SN1D, Operating Temperature Range="-55°C to +125°C", Tolerance_%=25%
FID1 FID2 FID3 FID4 FID5 FID6: library part CMP-0077181-1, "Fiducial mark.  There is nothing to buy or mount.", Manufacturer=N/A
J1 J3 J9 J10 J13 J14 J15 J16 J17 J18: library part CMP-0054566-1, "Header, 100mil, 2x1, Gold, TH", Color=Black, Current_A=3A, Manufacturer="Sullins Connector Solutions", Supplier Part Number 1=S1011E-02-ND, Voltage_V=1.8kV
J1/J3: library part CMP-0003837-4, "Receptacle, 2.54mm, 10x2, Tin, TH", Alternate Manufacturer="Major League Electronics", Alternate PartNumber=CRD-081413-A-G, Manufacturer=Samtec, Supplier Part Number 1=SAM1204-10-ND
J2: library part CMP-0080007-1, "Conncetor, micro SD, 8+2 Pos, R/A, SMT", Manufacturer="Hirose Electric Co. Ltd.", Supplier Part Number 1=HR1942CT-ND
J2/J4: library part CMP-0078266-4, "Receptacle, 2.54mm, 10x2, Tin, TH", Alternate Manufacturer="Major League Electronics", Alternate PartNumber=CRD-081413-A-G, Manufacturer=Samtec, Supplier Part Number 1=SAM1204-10-ND
J5: library part CMP-0093552-1, "USB-C (USB TYPE-C) USB 3.2 Gen 2 (USB 3.1 Gen 2, Superspeed + (USB 3.1)) Receptacle Connector 24 Position Surface Mount, Right Angle; Through Hole", Digikey Part Number=WM17992CT-ND, Manufacturer=Molex, Mouser Part Number=538-201267-0005, Operating Temperature Range="-40°C to +105°C", Voltage_V=30V
J5/J7: library part CMP-0081070-3, "Receptacle, 2.54mm, 10x2, Tin, TH", Alternate Manufacturer="Major League Electronics", Alternate PartNumber=CRD-081413-A-G, Manufacturer=Samtec, Supplier Part Number 1=SAM1204-10-ND
J6: library part CMP-0093156-1, Current_A=500mA, Digikey Part Number=HFK140CT-ND, Manufacturer=Hirose, Mouser Part Number=798-FH12A-40S0.5SH55, Operating Temperature Range="-40°C to +85°C", Voltage_V=50V
J6/J8: library part CMP-0081071-3, "Receptacle, 2.54mm, 10x2, Tin, TH", Alternate Manufacturer="Major League Electronics", Alternate PartNumber=CRD-081413-A-G, Manufacturer=Samtec, Supplier Part Number 1=SAM1204-10-ND
J7 J8: library part CMP-0093483-1, "RJ45 Connector with 1000 Base-TX Inetgrated Magnetic", Manufacturer=Link-PP, Operating Temperature Range="0°C to +70°C"
J11 J12: library part CMP-0002334-1, "Header, 100mil, 3x1, Gold, TH", Manufacturer="Sullins Connector Solutions", Supplier Part Number 1=S1011E-03-ND
J23: library part CMP-0080722-2, "Header, 2.54mm, 5x2, Gold, TH", Color=Black, Current_A=3A, Manufacturer="Sullins Connector Solutions", Supplier Part Number 1=S2011EC-05-ND, Voltage_V=1kV
J24 J25: library part CMP-0054597-1, "Header, 2.54mm, 5x1, Tin, TH", Color=Black, Current_A=3A, Manufacturer="Sullins Connector Solutions", Supplier Part Number 1=S1012E-05-ND, Voltage_V=1.8kV
J33: library part CMP-0075352-1, "Terminal Block, 3.5mm, 3x1, Tin, R/A, TH", Color=Blue, Current_A=10A, Manufacturer="On-Shore Technology", Supplier Part Number 1=ED2636-ND, Voltage_V=125V
J34: library part CMP-0055311-1, "Receptacle, USB 2.0, Micro B, 5 Position, R/A, SMT", Color=Black, Current_A=1.8A, Manufacturer=Molex, Supplier Part Number 1=WM11263CT-ND, Voltage_V=30V
L1: library part CMP-0003364-1, "Ferrite Bead, 30 ohm @ 100 MHz, 4 A, 0805", Manufacturer=MuRata, Supplier Part Number 1=490-11049-1-ND, Value1="0.014 ohm", Value2=4A, ValueDisplayed="30 ohm"
L2 L3: library part CMP-0064169-1, "Inductor, Shielded, 2.2 uH, 4.7 A, 0.029 ohm, SMD", Manufacturer="Wurth Elektronik", Supplier Part Number 1=732-8232-1-ND, Value1="0.029 ohm", Value2=4.7A, ValueDisplayed=2.2uH
L4: library part CMP-0078538-1, "10µH Semi-Shielded Wirewound Inductor 580mA 816 mOhm Max Nonstandard", Manufacturer="Wurth Electronics"
LBL1: library part CMP-0003625-1, "Thermal Transfer Printable Labels, 0.650\" W x 0.200\" H - 10,000 per roll", Manufacturer=Brady, Supplier Part Number 1=97C5133
Logo1: library part CMP-0074844-1
Logo2: library part CMP-0074838-1, "Texas Instrument Corporate Signature"
Logo3: library part CMP-0074847-1, "FCC_disclaimer"
Logo4: library part CMP-0074769-1
Q1 Q2 Q3: library part CMP-0078819-2, "MOSFET, P-CH, -12 V, -4.3 A, SOT-23", Alternate Manufacturer=None, Manufacturer="Infineon Technologies", Value1="0.05 ohm", Value2="10 nC"
Q4 Q5 Q6 Q7 Q8 Q9: library part CMP-0000947-2, "MOSFET, N-CH, 100 V, 0.17 A, SOT-23", Alternate Manufacturer=None, Manufacturer="Fairchild Semiconductor", Supplier Part Number 1=BSS123NCT-ND, Value1=1, Value2="1.8 nC"
Q10: library part CMP-0000010-3, "MOSFET, P-CH, -20 V, -0.39 A, SOT-323", Alternate Manufacturer=None, Manufacturer="Infineon Technologies", Value1=1
Q11 Q13: library part CMP-0000948-2, "MOSFET, N-CH, 100 V, 0.17 A, SOT-323", Alternate Manufacturer=None, Manufacturer="Diodes Inc.", Supplier Part Number 1=BSS123W-FDICT-ND, Value1=1
R1 R6 R8 R10 R11 R14 R15 R16 R17 R20 R42 R43 R92 R93 R98 R146 R147 R155 R156 R173 R174 R177 R178 R179 R181 R182 R183 R184 R185 R186 R187 R188 R194 R258 R268 R269 R270 R271 R274 R275 R276 R287 R288 R291 R292 R295 R296 R298 R299 R305 R306 R316 R318 R319 R320 R321 R322 R323 R374 R377: library part CMP-0026658-1, "RES, 10.0 k, 1%, 0.1 W, 0402", Manufacturer=Panasonic, Power_W=100mW, Supplier Part Number 1=P10.0KLCT-ND, TempCo="100 ppm/C", Tolerance_%=1%, Value2=0.1W, Value_Code=10k0, ValueDisplayed=10.0k
R2: library part CMP-0026240-2, "RES, 2.67 k, 1%, 0.063 W, AEC-Q200 Grade 0, 0402", Manufacturer=Vishay-Dale, Power_W=63mW, Supplier Part Number 1=541-2.67KLCT-ND, TempCo="100 ppm/C", Tolerance_%=1%, Value2=0.063W, Value_Code=2k67, ValueDisplayed=2.67k
R3 R4 R5 R7 R9 R12 R13 R18 R26 R33 R34 R35 R36 R37 R38 R44 R45 R46 R47 R48 R49 R50 R51 R52 R53 R54 R57 R58 R59 R60 R65 R66 R67 R68 R69 R70 R75 R76 R77 R78 R79 R80 R81 R82 R83 R84 R85 R86 R87 R88 R89 R90 R99 R100 R101 R102 R103 R104 R105 R106 R117 R118 R119 R129 R130 R131 R149 R150 R157 R158 R164 R165 R166 R167 R168 R169 R170 R171 R172 R180 R193 R196 R197 R198 R199 R200 R201 R212 R213 R214 R225 R227 R229 R231 R233 R235 R245 R248 R249 R280 R281 R282 R283 R284 R285 R286 R297 R307 R340 R341 R342 R343 R344 R345 R346 R347 R348 R349 R350 R351 R352 R353 R354 R355 R356 R357 R358 R359 R360 R361 R362 R363 R364 R365 R366 R367 R368 R376: library part CMP-0026992-3, "RES, 0, 5%, 0.1 W, AEC-Q200 Grade 0, 0402", Manufacturer=Panasonic, Power_W=100mW, Supplier Part Number 1=P0.0JCT-ND, TempCo="600 ppm/C", Tolerance_%=5%, Value2=0.1W, Value_Code=0000, ValueDisplayed=0
R19: library part CMP-0026703-1, "RES, 49.9, 1%, 0.1 W, AEC-Q200 Grade 0, 0402", Manufacturer=Panasonic, Power_W=100mW, Supplier Part Number 1=P49.9LCT-ND, TempCo="100 ppm/C", Tolerance_%=1%, Value2=0.1W, Value_Code=49R9, ValueDisplayed=49.9
R21 R22 R23 R24 R25 R96 R97 R256 R278 R289 R290 R293 R294 R300 R304: library part CMP-0078193-1, "RES, 1.0 k, 5%, 0.1 W, AEC-Q200 Grade 0, 0402", Manufacturer=Panasonic, Power_W=100mW, Supplier Part Number 1=P1.0KJCT-ND, TempCo="200 ppm/C", Tolerance_%=5%, Value2=0.1W, Value_Code=1k00, ValueDisplayed=1.0k
R27 R28 R29 R30 R61 R62 R71 R72 R369 R370 R371: library part CMP-0026696-1, "RES, 33.0, 1%, 0.1 W, 0402", Manufacturer=Panasonic, Power_W=100mW, Supplier Part Number 1=P33.0LCT-ND, TempCo="100 ppm/C", Tolerance_%=1%, Value2=0.1W, Value_Code=33R0, ValueDisplayed=33.0
R31 R195 R301 R336 R337 R375: library part CMP-0026659-2, "RES, 100 k, 1%, 0.1 W, 0402", Manufacturer=Panasonic, Power_W=100mW, TempCo="100 ppm/C", Tolerance_%=1%, Value2=0.1W, Value_Code=100k
R32 R253: library part CMP-0020616-3, "RES, 0, 5%, 0.125 W, AEC-Q200 Grade 0, 0805", Manufacturer=Panasonic, Power_W=125mW, Supplier Part Number 1=P0.0ACT-ND, TempCo="600 ppm/C", Tolerance_%=5%, Value2=0.125W, Value_Code=0000, ValueDisplayed=0
R39 R40 R41 R143 R244 R250 R338 R339: library part CMP-0025958-3, "RES, 10.0 k, 1%, 0.063 W, AEC-Q200 Grade 0, 0402", Manufacturer=Vishay-Dale, Power_W=63mW, Supplier Part Number 1=541-10.0KLCT-ND, TempCo="100 ppm/C", Tolerance_%=1%, Value2=0.063W, Value_Code=10k0, ValueDisplayed=10.0k
R55 R56 R63 R64 R73 R74 R95 R175 R176 R189 R190 R191 R192: library part CMP-0026938-5, "RES, 4.7 k, 5%, 0.063 W, AEC-Q200 Grade 0, 0402", Manufacturer=Vishay-Dale, Power_W=63mW, Supplier Part Number 1=541-4.7KJCT-ND, TempCo="200 ppm/C", Tolerance_%=5%, Value2=0.063W, Value_Code=4k70, ValueDisplayed=4.7k
R91: library part CMP-0026873-2, "RES, 200 k, 5%, 0.063 W, AEC-Q200 Grade 0, 0402", Manufacturer=Vishay-Dale, Power_W=63mW, Supplier Part Number 1=541-200KJCT-ND, TempCo="200 ppm/C", Tolerance_%=5%, Value2=0.063W, Value_Code=200k
R94: library part CMP-0026603-2, "RES, 909 k, 1%, 0.063 W, AEC-Q200 Grade 0, 0402", Manufacturer=Vishay-Dale, Power_W=63mW, Supplier Part Number 1=541-909KLCT-ND, TempCo="100 ppm/C", Tolerance_%=1%, Value2=0.063W, Value_Code=909k
R107 R202: library part CMP-0082348-1, "RES, 11.5 k, 1%, 0.1 W, AEC-Q200 Grade 0, 0402", Manufacturer=Panasonic, Power_W=100mW, TempCo="100 ppm/C", Tolerance_%=1%, Value2=0.1W, Value_Code=11k5, ValueDisplayed=11.5k
R108 R109 R110 R111 R112 R113 R114 R115 R116 R120 R121 R122 R123 R124 R125 R126 R127 R128 R153 R203 R204 R205 R206 R207 R208 R209 R210 R211 R215 R216 R217 R218 R219 R220 R221 R222 R223: library part CMP-0026237-2, "RES, 2.49 k, 1%, 0.063 W, AEC-Q200 Grade 0, 0402", Manufacturer=Vishay-Dale, Power_W=63mW, Supplier Part Number 1=541-2.49KLCT-ND, TempCo="100 ppm/C", Tolerance_%=1%, Value2=0.063W, Value_Code=2k49, ValueDisplayed=2.49k
R132: library part CMP-0026993-2, "RES, 100, 5%, 0.1 W, AEC-Q200 Grade 0, 0402", Manufacturer=Panasonic, Power_W=100mW, Supplier Part Number 1=P100JCT-ND, TempCo="200 ppm/C", Tolerance_%=5%, Value2=0.1W, Value_Code=100R, ValueDisplayed=100
R133 R134 R135 R324 R325 R326 R327 R328 R329 R330 R331 R332 R333 R334 R335: library part CMP-0026299-2, "RES, 33.2, 1%, 0.063 W, AEC-Q200 Grade 0, 0402", Manufacturer=Vishay-Dale, Power_W=63mW, Supplier Part Number 1=541-33.2LCT-ND, TempCo="100 ppm/C", Tolerance_%=1%, Value2=0.063W, Value_Code=33R2, ValueDisplayed=33.2
R136 R137: library part CMP-0078210-2, "RES, 330 k, 1%, 0.063 W, AEC-Q200 Grade 0, 0402", Manufacturer=Vishay-Dale, Power_W=63mW, Supplier Part Number 1=541-330KLCT-ND, TempCo="100 ppm/C", Tolerance_%=1%, Value2=0.063W, Value_Code=330k
R138 R139 R140 R141 R144 R261 R308 R309 R310 R311 R312: library part CMP-0026071-3, "RES, 1.00 k, 1%, 0.063 W, AEC-Q200 Grade 0, 0402", Manufacturer=Vishay-Dale, Power_W=63mW, Supplier Part Number 1=541-1.00KLCT-ND, TempCo="100 ppm/C", Tolerance_%=1%, Value2=0.063W, Value_Code=1k00, ValueDisplayed=1.00k
R142: library part CMP-0026404-2, "RES, 49.9, 1%, 0.063 W, AEC-Q200 Grade 0, 0402", Manufacturer=Vishay-Dale, Power_W=63mW, Supplier Part Number 1=541-49.9LCT-ND, TempCo="100 ppm/C", Tolerance_%=1%, Value2=0.063W, Value_Code=49R9, ValueDisplayed=49.9
R145: library part CMP-0026413-2, "RES, 4.87 k, 1%, 0.063 W, AEC-Q200 Grade 0, 0402", Manufacturer=Vishay-Dale, Power_W=63mW, Supplier Part Number 1=541-4.87KLCT-ND, TempCo="100 ppm/C", Tolerance_%=1%, Value2=0.063W, Value_Code=4k87, ValueDisplayed=4.87k
R148 R160: library part CMP-0021602-3, "RES, 18.2 k, 1%, 0.125 W, AEC-Q200 Grade 0, 0805", Manufacturer=Panasonic, Power_W=125mW, Supplier Part Number 1=P18.2KCCT-ND, TempCo="100 ppm/C", Tolerance_%=1%, Value2=0.125W, Value_Code=18k2, ValueDisplayed=18.2k
R151: library part CMP-0026336-2, "RES, 3.57 k, 1%, 0.063 W, AEC-Q200 Grade 0, 0402", Manufacturer=Vishay-Dale, Power_W=63mW, Supplier Part Number 1=541-3.57KLCT-ND, TempCo="100 ppm/C", Tolerance_%=1%, Value2=0.063W, Value_Code=3k57, ValueDisplayed=3.57k
R152: library part CMP-0026093-3, "RES, 1.69 k, 1%, 0.063 W, AEC-Q200 Grade 0, 0402", Manufacturer=Vishay-Dale, Power_W=63mW, Supplier Part Number 1=541-1.69KLCT-ND, TempCo="100 ppm/C", Tolerance_%=1%, Value2=0.063W, Value_Code=1k69, ValueDisplayed=1.69k
R154 R161 R163 R373: library part CMP-0026414-2, "RES, 4.99 k, 1%, 0.063 W, AEC-Q200 Grade 0, 0402", Manufacturer=Vishay-Dale, Power_W=63mW, Supplier Part Number 1=541-4.99KLCT-ND, TempCo="100 ppm/C", Tolerance_%=1%, Value2=0.063W, Value_Code=4k99, ValueDisplayed=4.99k
R159: library part CMP-0026097-2, "RES, 1.87 k, 1%, 0.063 W, AEC-Q200 Grade 0, 0402", Manufacturer=Vishay-Dale, Power_W=63mW, Supplier Part Number 1=541-1.87KLCT-ND, TempCo="100 ppm/C", Tolerance_%=1%, Value2=0.063W, Value_Code=1k87, ValueDisplayed=1.87k
R162: library part CMP-0026028-3, "RES, 15.4 k, 1%, 0.063 W, AEC-Q200 Grade 0, 0402", Manufacturer=Vishay-Dale, Power_W=63mW, Supplier Part Number 1=541-15.4KLCT-ND, TempCo="100 ppm/C", Tolerance_%=1%, Value2=0.063W, Value_Code=15k4, ValueDisplayed=15.4k
R224 R226 R228 R230 R232 R234: library part CMP-0026878-3, "RES, 220, 5%, 0.063 W, AEC-Q200 Grade 0, 0402", Manufacturer=Vishay-Dale, Power_W=63mW, Supplier Part Number 1=541-220JCT-ND, TempCo="200 ppm/C", Tolerance_%=5%, Value2=0.063W, Value_Code=220R, ValueDisplayed=220
R236 R237 R238 R239 R240 R241 R242 R243: library part CMP-0026702-1, "RES, 49.9 k, 1%, 0.1 W, AEC-Q200 Grade 0, 0402", Manufacturer=Panasonic, Power_W=100mW, Supplier Part Number 1=P49.9KLCT-ND, TempCo="100 ppm/C", Tolerance_%=1%, Value2=0.1W, Value_Code=49k9, ValueDisplayed=49.9k
R246 R247: library part CMP-0026491-2, "RES, 61.9, 1%, 0.063 W, AEC-Q200 Grade 0, 0402", Manufacturer=Vishay-Dale, Power_W=63mW, Supplier Part Number 1=541-61.9LCT-ND, TempCo="100 ppm/C", Tolerance_%=1%, Value2=0.063W, Value_Code=61R9, ValueDisplayed=61.9
R251: library part CMP-0026437-2, "RES, 51.1 k, 1%, 0.063 W, AEC-Q200 Grade 0, 0402", Manufacturer=Vishay-Dale, Power_W=63mW, Supplier Part Number 1=541-51.1KLCT-ND, TempCo="100 ppm/C", Tolerance_%=1%, Value2=0.063W, Value_Code=51k1, ValueDisplayed=51.1k
R252: library part CMP-0078244-2, "RES, 30.0 k, 1%, 0.063 W, AEC-Q200 Grade 0, 0402", Manufacturer=Vishay-Dale, Power_W=63mW, Supplier Part Number 1=541-30.0KLCT-ND, TempCo="100 ppm/C", Tolerance_%=1%, Value2=0.063W, Value_Code=30k0, ValueDisplayed=30.0k
R254 R255: library part CMP-0021522-3, "RES, 1.00 M, 1%, 0.125 W, AEC-Q200 Grade 0, 0805", Manufacturer=Panasonic, Power_W=125mW, Supplier Part Number 1=P1.00MCCT-ND, TempCo="100 ppm/C", Tolerance_%=1%, Value2=0.125W, Value_Code=1M00, ValueDisplayed=1.00M
R257: library part CMP-0026704-1, "RES, 510, 1%, 0.1 W, 0402", Manufacturer=Panasonic, Power_W=100mW, Supplier Part Number 1=P510LCT-ND, TempCo="100 ppm/C", Tolerance_%=1%, Value2=0.1W, Value_Code=510R, ValueDisplayed=510
R259 R260 R265 R302 R314: library part CMP-0078194-1, "RES, 360, 5%, 0.1 W, AEC-Q200 Grade 0, 0402", Manufacturer=Panasonic, Power_W=100mW, Supplier Part Number 1=P360JCT-ND, TempCo="200 ppm/C", Tolerance_%=5%, Value2=0.1W, Value_Code=360R, ValueDisplayed=360
R262 R263 R264 R266 R267 R273 R277 R279: library part CMP-0026680-1, "RES, 220, 1%, 0.1 W, AEC-Q200 Grade 0, 0402", Manufacturer=Panasonic, Power_W=100mW, Supplier Part Number 1=P220LCT-ND, TempCo="100 ppm/C", Tolerance_%=1%, Value2=0.1W, Value_Code=220R, ValueDisplayed=220
R272 R303 R317: library part CMP-0078212-1, "RES, 510, 5%, 0.1 W, AEC-Q200 Grade 0, 0402", Manufacturer=Panasonic, Power_W=100mW, Supplier Part Number 1=P510JCT-ND, TempCo="200 ppm/C", Tolerance_%=5%, Value2=0.1W, Value_Code=510R, ValueDisplayed=510
R313 R315: library part CMP-0025998-3, "RES, 130, 1%, 0.063 W, AEC-Q200 Grade 0, 0402", Manufacturer=Vishay-Dale, Power_W=63mW, Supplier Part Number 1=541-130LCT-ND, TempCo="100 ppm/C", Tolerance_%=1%, Value2=0.063W, Value_Code=130R, ValueDisplayed=130
R372: library part CMP-0025960-3, "RES, 10.5 k, 1%, 0.063 W, AEC-Q200 Grade 0, 0402", Manufacturer=Vishay-Dale, Power_W=63mW, Supplier Part Number 1=541-10.5KLCT-ND, TempCo="100 ppm/C", Tolerance_%=1%, Value2=0.063W, Value_Code=10k5, ValueDisplayed=10.5k
S1: library part CMP-0002139-2, "Switch, Slide, SPDT  100mA, SMT", CurrentRating_mA=100A, Manufacturer="Copal Electronics", Supplier Part Number 1=CAS120JCT-ND
S2: library part CMP-0002233-1, "Switch, Dual SPDT,  2 Pos, 0.1A, 6VDC, SMD", CurrentRating_mA=100A, Manufacturer="Copal Electronics", Supplier Part Number 1=CASD20JCT-ND
SH-J1 SH-J2 SH-J3 SH-J4 SH-J5 SH-J6 SH-J7 SH-J8: library part CMP-0003761-2, "Shunt, 2.54mm, Gold, Black", Manufacturer="Wurth Elektronik", Supplier Part Number 1=732-2678-ND
SW1: library part CMP-0093176-1, "Dip Switch SPST 4 Position Surface Mount Slide (Standard) Actuator 25mA 24VDC", Coil Resistance_ohm=100mΩ, Contact Current Rating=25mA, Digikey Part Number=732-3854-1-ND, Manufacturer=Wurth, Mouser Part Number=710-416131160804, Operating Temperature Range="-40°C to +85°C"
SW2 SW3 SW4: library part CMP-0093456-1, "Tactile Switch SPST-NO Side Actuated Surface Mount, Right Angle", Coil Resistance_ohm=100mΩ, Contact Current Rating=50mA, Digikey Part Number=732-7057-1-ND, Manufacturer="Wurth Electronics", Mouser Part Number=710-434351045816, Operating Force=160gf, Operating Temperature Range="-40°C to +85°C"
TP1 TP2: library part CMP-0003825-1, "1mm Test Point, SMT", Manufacturer=Any
TP3 TP4 TP5 TP6 TP7 TP8 TP9 TP10 TP11 TP12 TP13 TP14 TP15 TP16 TP17 TP18 TP19 TP20 TP21 TP22 TP23 TP24 TP25 TP26 TP27 TP28 TP29 TP30: library part CMP-0078143-3, "TEST POINT.  No entry in BOM.", Manufacturer=N/A
U1: library part AM263x, "Sitara AM263x MCU", Manufacturer="Texas Instruments"
U2: library part CMP-0051219-1, "Single 3-Input Positive-AND Gate, DBV0006A, LARGE T&R", F @ Nom Voltage(Max)(Mhz)=150, Generic Part Number=SN74LVC1G11, ICC @ Nom Voltage(Max)(mA)=0.01, Manufacturer="Texas Instruments", Operating Temperature Range(C)="-40 to 125,-40 to 85", Rating=Catalog, tpd @ Nom Voltage(Max)(ns)=20,7.8,6.2,4.6, Voltage(Nom)(V)=1.8,2.5,3.3,5
U3: library part CMP-0043157-2, "Low-Voltage 8-Bit I2C and SMBus I/O Expander, 1.65 to 5.5 V, -40 to 85 degC, 16-pin QFN (RGT), Green (RoHS & no Sb/Br)", 5V Tolerant I/O=Yes, Manufacturer="Texas Instruments", Max Frequency(kHz)=400
U4: library part CMP-0066450-2, "4-Bit Dual-Supply Bus Transceiver with Configurable Voltage-Level Shifting and 3-State Outputs, RSV0016A (UQFN-16)", Alternate Manufacturer="Texas Instruments"
U5 U9 U47: library part CMP-0051588-2, "Single 2-Input Positive-AND Gate, DBV0005A, LARGE T&R", Alternate Manufacturer="Texas Instruments", F @ Nom Voltage(Max)(Mhz)=150, Generic Part Number=SN74LVC1G08, ICC @ Nom Voltage(Max)(mA)=0.01, Operating Temperature Range(C)="-40 to 125,-40 to 85", Rating=Catalog, tpd @ Nom Voltage(Max)(ns)=4.5,6,4,5, Voltage(Nom)(V)=1.8,2.5,3.3,5
U6: library part CMP-0051704-3, "Single Schmitt-Trigger Buffer, DCK0005A, LARGE T&R", F @ Nom Voltage(Max)(Mhz)=150, Generic Part Number=SN74LVC1G17, ICC @ Nom Voltage(Max)(mA)=0.01, Manufacturer="Texas Instruments", Operating Temperature Range(C)="-40 to 125,-40 to 85", Rating=Catalog, tpd @ Nom Voltage(Max)(ns)=11,6.5,5.5,5, Voltage(Nom)(V)=1.8,2.5,3.3,5
U7: library part CMP-0093537-1, "FLASH - NOR Memory IC 128Mb (16M x 8) SPI - Quad I/O 133 MHz 8-WSON (6x8)", Digikey Part Number=1274-1178-ND, Frequency_Fixed=133MHz, Manufacturer="Cypress Semiconductor", Max Supply Voltage=3.6V, Min Supply Voltage=1.65V, Mouser Part Number=797-25FL128SAGNFI000, Nominal Supply Current=16-100mA, Operating Temperature Range="-40°C to +85°C"
U8: library part CMP-0081995-1, "5.5V, 2A, 52mΩ Automotive High-Side Load Switch with Adjustable Rise Time & Quick Output Discharge, DBV0006A (SOT-23-6)", Alternate Manufacturer="Texas Instruments", Alternate PartNumber=TPS22918TDBVRQ1, Operating Temperature Range="-40 to 105 C", Rating=Automotive
U10: library part CMP-0043096-2, "Low-Capacitance + / - 15 kV ESD-Protection Array for High-Speed Data Interfaces, 2 Channels, -40 to +85 degC, 5-pin SOT (DRL), Green (RoHS & no Sb/Br)", Breakdown Voltage(Min)(V)=11, IO Capacitance(Typ)(pF)=1.5, IO Leakage Current(nA)=1, Manufacturer="Texas Instruments"
U11: library part CMP-0043123-1, "Low-Capacitance + / - 15 kV ESD Protection Array for High-Speed Data Interfaces, 6 Channels, -40 to +85 degC, 10-pin UQFN (RSE), Green (RoHS & no Sb/Br)", Breakdown Voltage(Min)(V)=11, IO Capacitance(Typ)(pF)=1.5, IO Leakage Current(nA)=1, Manufacturer="Texas Instruments"
U12 U13 U14 U15 U20 U44: library part CMP-0073612-3, "4-Channel ESD Protection Diode for USB Type-C and HDMI 2.0, DQA0010A (USON-10)", Alternate Manufacturer="Texas Instruments"
U16: library part CMP-0005327-2, "1024-Kb I2C CMOS Serial EEPROM, SOIC-8", Manufacturer="ON Semiconductor", Supplier Part Number 1=CAT24M01WI-GT3OSTR-ND
U17: library part CMP-0067419-2, "2-Channel, 2:1 Analog Switch with Low On-State Resistance (1ohm) and Powered Off Protection, DGS0010A (VSSOP-10)", Alternate Manufacturer="Texas Instruments", Alternate PartNumber=TS5A23159DGST, Operating Temperature Range="-40 to 85 C", Rating=Catalog
U18: library part CMP-0073635-2, "USB Type-C Configuration Channel Logic and Port Control, RWB0012A (X2QFN-12)", Alternate Manufacturer="Texas Instruments", Operating Temperature Range="-40 to 85 C", Rating=Catalog
U19: library part CMP-0073678-3, "5.5V, 4A, 16mΩ Automotive Load Switch With Adjustable Rise Time and Optional Quick Output Discharge, DSG0008B (WSON-8)", Alternate Manufacturer="Texas Instruments", Alternate PartNumber=TPS22965TDSGTQ1
U21: library part CMP-0051530-2, "Single 2-Input Positive-NOR Gate, DRL0005A, LARGE T&R", Alternate Manufacturer="Texas Instruments", F @ Nom Voltage(Max)(Mhz)=75, Generic Part Number=SN74AHC1G02, ICC @ Nom Voltage(Max)(mA)=0.01, Operating Temperature Range(C)="-40 to 125,-40 to 85", Rating=Catalog, tpd @ Nom Voltage(Max)(ns)=11.4,7.5, Voltage(Nom)(V)=3.3,5
U22 U37: library part CMP-0091377-1, "1/1 Transceiver Ethernet 48-VQFN (7x7)", Digikey Part Number=296-53377-1-ND, Manufacturer="Texas Instruments", Max Supply Voltage=3.45V, Min Supply Voltage=990mV, Mouser Part Number=595-DP83869HMRGZT, Operating Temperature Range="-40°C to +125°C"
U23 U50 U52: library part CMP-0093539-2, "IC MUX/DEMUX DDR3 1:2 42WQFN", Digikey Part Number=296-28307-1-ND, Manufacturer="Texas Instruments", Max Supply Voltage=3.6V, Min Supply Voltage=3V, Mouser Part Number=595-TS3DDR3812RUAR, Nominal Supply Current=300uA, On State Resistance=8Ω, Operating Temperature Range="-40°C to +85°C"
U24: library part CMP-0029856-2, "Tiva C Series Microcontroller, 1024 KB Flash, 256 KB SRAM, 12 Bit, 20 Channels, -40 to 105 degC, 128-Pin TQFP (PDT), Green (RoHS & no Sb/Br), Tray", Manufacturer="Texas Instruments", Temperature Range="-40 to 105 degC"
U25: library part CMP-0029369-1, "25 Mbps Dual Channels, 2 / 0, Digital Isolator, 3.3 V / 5 V, -40 to +125 degC, 8-pin SOIC (D), Green (RoHS & no Sb/Br)", Insulation Rating(VRMS)=2500, Manufacturer="Texas Instruments", Rating=Catalog, Supply Voltage(s)(V)="3.3, 5"
U26 U27: library part CMP-0076059-2, "High Speed, Robust EMC Dual-Channel Digital Isolator, D0008B (SOIC-8)", Alternate Manufacturer="Texas Instruments", Alternate PartNumber=ISO7721D, Operating Temperature Range="-55 to 125 C", Rating=Catalog
U28: library part CMP-0033001-1, "Precision Micropower Shunt Voltage Reference, 0.5% accuracy, 2.5 V, 15 ppm / degC, 15 mA, -40 to 125 degC, 3-pin SOT-23 (DBZ), Green (RoHS & no Sb/Br)", Manufacturer="Texas Instruments", Rating=Catalog, Temp Coeff(Max)(ppm/ degree C)=100, Temp Coeff(Typ)(ppm/ degree C)=15
U29 U32: library part CMP-0089785-1, "3V to 17V, 3A Micro Noise (20µVRMS) and Micro Ripple (200µVPP) buck converter", Manufacturer="Texas Instruments", Max Supply Voltage=17V, Min Supply Voltage=3V, Nominal Supply Current=5mA, Operating Temperature Range="-40°C to +150°C", Output Voltage=0.8-5.5V, Switching Frequency=1/2.2MHz
U30 U31: library part CMP-0036365-5, "Single Output LDO, 1.5A, Adj. (0.8 to 3.6V), Programmable Soft-Start, DRC0010J (VSON-10)", Manufacturer="Texas Instruments", Operating Temperature Range="-40 to 125 C", Power Good=TRUE, Rating=Catalog
U33: library part CMP-0051392-2, "Single Buffer/Driver With Open-Drain Output, DCK0005A, SMALL T&R", F @ Nom Voltage(Max)(Mhz)=150, Generic Part Number=SN74LVC1G07, ICC @ Nom Voltage(Max)(mA)=0.01, Manufacturer="Texas Instruments", Operating Temperature Range(C)="-40 to 125,-40 to 85", Rating=Catalog, tpd @ Nom Voltage(Max)(ns)=8.6,6,4.7,4, Voltage(Nom)(V)=1.8,2.5,3.3,5
U34: library part CMP-0051904-4, "Dual Schmitt-Trigger Buffer, DSF0006A, LARGE T&R", F @ Nom Voltage(Max)(Mhz)=150, Generic Part Number=SN74LVC2G17, ICC @ Nom Voltage(Max)(mA)=0.01, Manufacturer="Texas Instruments", Operating Temperature Range(C)="-40 to 125,-40 to 85", Rating=Catalog, tpd @ Nom Voltage(Max)(ns)=9.3,5.7,5.4,4.3, Voltage(Nom)(V)=1.8,2.5,3.3,5
U35: library part CMP-0076016-2, "Level-Translating I2C Bus Repeater, DGK0008A (VSSOP-8)", Alternate Manufacturer="Texas Instruments"
U36: library part CMP-0067107-3, "28V, 0.5A Step-Down Converter with SNOOZE Mode, DQC0010A (WSON-10)", Alternate Manufacturer="Texas Instruments", Alternate PartNumber=TPS62177DQCT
